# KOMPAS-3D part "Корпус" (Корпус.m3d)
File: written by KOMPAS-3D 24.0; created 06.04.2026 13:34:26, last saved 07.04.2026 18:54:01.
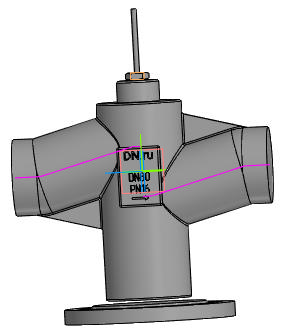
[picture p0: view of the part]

Document properties: Автор: R2D2; Полное имя файла: E:\Работа\Зайцев\Солянка\VSR1-13V-PED-F Клапан запорно-регулирующий DN.ru\DN80\исходные материалы\Корпус.m3d

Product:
- Body: Труба / Нестандартная труба / L = 153.9 мм  | qty 1
    Материал: Нестандартная труба (density 7856 kg/m3)
    Масса: 25.886143
    Раздел спецификации: Детали
    Примечание: 7,69 кг
    additional columns: Pipeline; 0.09; 0; 0; 0.002; 0.15386; true; 0.04
- Body: Труба / Нестандартная труба / L = 153.9 мм  | qty 1
    Материал: Нестандартная труба (density 7856 kg/m3)
    Масса: 25.886143
    Раздел спецификации: Детали
    Форматы листов документа: БЧ
    Примечание: 7,69 кг
    additional columns: Pipeline; 0.09; 0; 0; 0.002; 0.15386; true; 0.04
- Component [standard]: Гайка М16-6H ГОСТ 5916-70  | qty 1  | Масса: 0.01768; Рассекать на разрезах: no; source file: C:\Program Files\ASCON\KOMPAS-3D v24\Libs\PolynomLib\DATA\vault\Methods\Kompas\3D\PLib_Nut_OST92_900.m3d
- Component [standard]: (unnamed)  | qty 1  | Материал: ВЧ40 ГОСТ 7293-85 (density 7200 kg/m3); Масса: 3.909961; Рассекать на разрезах: no; additional columns: 80-16-B-2-ВЧ40-II; Заглушка; ГОСТ 34785-2021
- Body: Тело 4  | qty 1
    Материал: Нестандартная труба (density 7856 kg/m3)
    Масса: 25.886143
- Part/product: Корпус
    Масса: 6.9

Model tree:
1. Эскиз:1
2. Труба:1  (labels: {F703FF30-5BE6-4673-A7F1-8EDA1BE1E2D1}; SHAPEOBJECT3D_ATTR_BUTT; SHAPEOBJECT3D_ATTR_VALID; SHAPEOBJECT3D_ATTR_BUTT_AREA)
     PIPE_R = 7
3. Труба:2  (labels: {F703FF30-5BE6-4673-A7F1-8EDA1BE1E2D1}; SHAPEOBJECT3D_ATTR_BUTT; SHAPEOBJECT3D_ATTR_VALID; SHAPEOBJECT3D_ATTR_BUTT_AREA)
     PIPE_R = 7
4. Эскиз:2
5. Элемент выдавливания:1
     Расстояние 1 = 107; Смещение 1 = -1; Расстояние 2 = 150; Смещение 2 = -5
6. РЕБРО  (with: Ребро.Труба:1, Грань.Элемент выдавливания:1, Грань.Труба:1, Грань.Труба:2)
7. Элемент выдавливания:2
     Расстояние 1 = 6
8. Эскиз:4  (with: Грань.Элемент выдавливания:1)
9. Скругление:3  (with: Ребро.Элемент выдавливания:2)
10. Элемент выдавливания:3
     Расстояние 1 = 1
11. Эскиз:5  (with: Грань.Элемент выдавливания:3)
12. Элемент выдавливания:4
     Расстояние 1 = 7.5; Смещение 1 = 0.5
13. ШТОК
14. Элемент выдавливания:5
15. ОТЛИВКА
16. Скругление:6  (with: Грань.Элемент выдавливания:1)
17. Элемент выдавливания:6  (with: Грань.Элемент выдавливания:1)
     Смещение 1 = 4
18. ТЕКСТ  (with: Грань.Элемент выдавливания:6)
19. Элемент выдавливания:7
     Расстояние 1 = 0.5
20. Скругление:7  (with: Ребро.Элемент выдавливания:6)
     Радиус = 2
21. Эскиз:9  (with: Грань.Элемент выдавливания:1, Ребро.Скругление:6, Ребро.Элемент выдавливания:5)
22. Элемент вращения:1
     Угол 1 = 360
23. Скругление:8  (with: Ребро.Элемент вращения:1, Грань.Элемент выдавливания:3)
     Радиус = 2

Expressions: DS/2+3; v22*2
Referenced files in C:\Program Files\ASCON\KOMPAS-3D v24\Libs\Pipeline\: StylesTemplate.a3d, TemplateHPH, InsulationStylesTemplate.a3d, Insulation
Referenced files in C:\Program Files\ASCON\KOMPAS-3D v24\Templates\: Констр. чертеж А3 гориз. перв. лист.cdt
Referenced files in E:\Работа\Зайцев\Солянка\VSR1-13V-PED-F Клапан запорно-регулирующий DN.ru\DN15\DN15 Kv0.16\исходные материалы\: 
Referenced files in C:\Program Files\ASCON\KOMPAS-3D v24\Libs\PolynomLib\DATA\vault\Methods\Kompas\3D\: PLib_Nut_OST92_900.m3d, PLib_Flange_Blind_GOST_34785_2100.m3d
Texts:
  Отводы ГОСТ 17375-2001
  Констр. чертеж А3 гориз. перв. лист.cdt
  BOSimple***PART:2c8e7818-1586-f79e-db7d-bc045ba468e4***SHORTLOC:Root±30±10±20±©{}110±10±50±80[Нет;Без покрытия;Без указания материала;-;16;2;24]
  BOSimple***Material:38d6725a-5efe-48e1-b177-a7817acb862a
  BOSimple***PART:34d5ed0f-b667-c2a1-0512-09aa6b693dca***SHORTLOC:B619_EF039B503CC34112[2;16;80;Круглая;II;ВЧ40 ГОСТ 7293-85]
  var3D
  PN16
  LL-10
  DN+10
  bcut1
  hole1
  hcut1
  hole2
  cut1
  Труба / Нестандартная труба / L = %s мм
  Plane. Начало координат
  Ось Y.Начало координат
  Плоскость ZX.Начало координат
  Горизонтальная плоскость. Начало координат
  Плоскость XY.Начало координат
  Плоскость ZY.Начало координат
